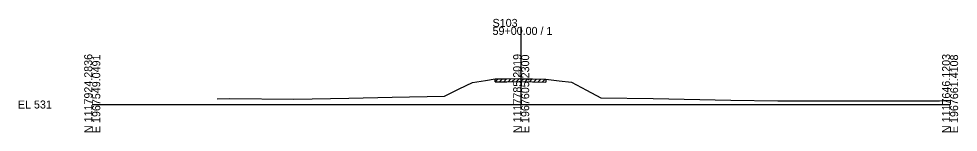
# Model space of a CAD drawing. Extents: x 974 to 1303, y 990 to 14518.
# Drawn here: x 974.3 to 1302.8, y 5490.3 to 5530 of the extents above; entities that cross this region are included whole.
import ezdxf

# ---------------------------------------------------------------- set-up
doc = ezdxf.new("R2010")
doc.units = 0
for name, color, linetype in [('Level 10', 7, 'Continuous'), ('Level 60', 7, 'Continuous'), ('Level 61', 7, 'Continuous'), ('Level 63', 7, 'Continuous')]:
    doc.layers.add(name, color=color, linetype=linetype)

msp = doc.modelspace()

# ---------------------------------------------------------------- linework, layer by layer
at = {"layer": 'Level 60'}
for p, q in [((1128.26, 5505.45), (1132.92, 5507.73)), ((1132.92, 5507.73), (1137.49, 5508.44)), ((1137.49, 5508.44), (1140.9, 5508.93)), ((1140.9, 5508.93), (1144.95, 5508.99)), ((1144.95, 5508.99), (1149.28, 5509.05)), ((1149.28, 5509.05), (1150, 5509.04)), ((1150, 5509.04), (1153.95, 5508.95)), ((1153.95, 5508.95), (1158.61, 5508.87)), ((1158.61, 5508.87), (1163.26, 5508.31)), ((1163.26, 5508.31), (1167.63, 5507.85)), ((1167.63, 5507.85), (1172.89, 5505)), ((1104.88, 5502.56), (1123.2, 5502.97)), ((1123.2, 5502.97), (1128.26, 5505.45)), ((1172.89, 5505), (1177.85, 5502.31)), ((1043.66, 5501.97), (1047.94, 5502.06)), ((1047.94, 5502.06), (1070.46, 5501.89)), ((1070.46, 5501.89), (1089.76, 5502.22)), ((1089.76, 5502.22), (1104.88, 5502.56)), ((1177.85, 5502.31), (1196.16, 5502.09)), ((1196.16, 5502.09), (1223.28, 5501.54)), ((1223.28, 5501.54), (1239.73, 5501.25)), ((1239.73, 5501.25), (1296.25, 5501.34)), ((1296.25, 5501.34), (1300, 5501.49))]:
    msp.add_line(p, q, dxfattribs=at)
at = {"layer": 'Level 61'}
for p, q in [((1140.9, 5507.93), (1141.92, 5508.94)), ((1140.9, 5507.93), (1140.9, 5508.93)), ((1140.9, 5507.93), (1144.95, 5507.99)), ((1140.9, 5507.93), (1140.9, 5507.93)), ((1142.4, 5507.95), (1143.42, 5508.97)), ((1143.9, 5507.97), (1144.92, 5508.99)), ((1144.95, 5507.99), (1149.28, 5508.05)), ((1145.4, 5507.99), (1146.42, 5509.01)), ((1146.9, 5508.02), (1147.92, 5509.03)), ((1148.4, 5508.04), (1149.41, 5509.05)), ((1149.28, 5508.05), (1150, 5508.04)), ((1149.9, 5508.04), (1150.88, 5509.02)), ((1150, 5508.04), (1153.95, 5507.95)), ((1151.4, 5508), (1152.38, 5508.98)), ((1152.9, 5507.97), (1153.88, 5508.95)), ((1153.95, 5507.95), (1158.61, 5507.87)), ((1154.4, 5507.94), (1155.39, 5508.92)), ((1155.9, 5507.91), (1156.89, 5508.9)), ((1157.4, 5507.89), (1158.39, 5508.87)), ((1158.61, 5508.87), (1158.61, 5507.87))]:
    msp.add_line(p, q, dxfattribs=at)
at = {"layer": 'Level 63'}
for p, q in [((1150, 5500), (1150, 5527.15)), ((1000, 5500), (1150, 5500)), ((1150, 5500), (1300, 5500))]:
    msp.add_line(p, q, dxfattribs=at)

# ---------------------------------------------------------------- texts
at = {"layer": 'Level 10'}
msp.add_text('540.04', height=0.9, rotation=90, dxfattribs=at).set_placement((1149.95, 5509.54))
at = {"layer": 'Level 63'}
for s, p in [('S103', (1140, 5527.15)), ('59+00.00 / 1', (1140, 5524.35)), ('EL 531', (974, 5498.6))]:
    msp.add_text(s, height=2.8, dxfattribs=at).set_placement(p)
for s, p in [('N 1117924.2836', (1000, 5490)), ('E 1967549.0491', (1002.8, 5490)), ('N 1117785.2019', (1150, 5490)), ('E 1967605.2300', (1152.8, 5490)), ('N 1117646.1203', (1300, 5490)), ('E 1967661.4108', (1302.8, 5490))]:
    msp.add_text(s, height=2.8, rotation=90, dxfattribs=at).set_placement(p)

doc.saveas('drawing.dxf')
